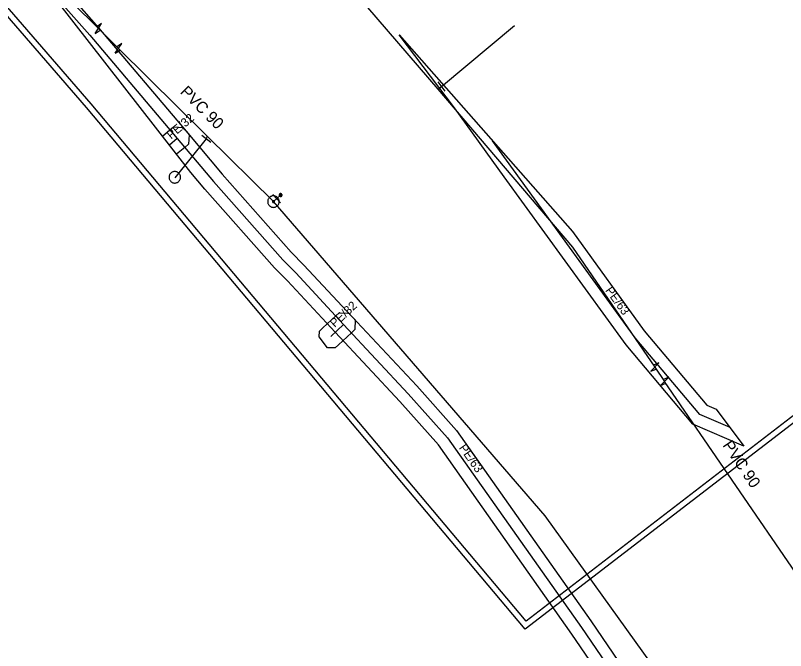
# Model space of a CAD drawing. Extents: x -743072 to -742584, y -978827 to -978325.
# Drawn here: x -742873.3 to -742806.2, y -978569.2 to -978513.9 of the extents above; entities that cross this region are included whole.
import ezdxf

# ---------------------------------------------------------------- set-up
doc = ezdxf.new("R2010")
doc.units = 0
for name, color, linetype in [('IS_CETIN_sdělovací kabel_nadz', 7, 'Continuous'), ('IS_GasNet_ochr pasmo', 7, 'Continuous'), ('IS_GasNet_plyn STL', 7, 'Continuous'), ('IS_Obec_kabel VO_nadz', 7, 'Continuous'), ('IS_popis_GasNet', 7, 'Continuous'), ('IS_popis_ScVK', 7, 'Continuous'), ('IS_ScVK_Kanal_dest', 7, 'Continuous'), ('IS_ScVK_Vodovod', 7, 'Continuous')]:
    doc.layers.add(name, color=color, linetype=linetype)

msp = doc.modelspace()

# ---------------------------------------------------------------- linework, layer by layer
at = {"layer": 'IS_CETIN_sdělovací kabel_nadz'}
msp.add_lwpolyline([(-742799.79, -978544.98), (-742828.86, -978567.32), (-742867.05, -978521.91), (-742897.64, -978486.54), (-742872.63, -978477.97), (-742862.09, -978471.14)], dxfattribs=at)
at = {"layer": 'IS_GasNet_ochr pasmo'}
for points in [[(-742816.226, -978580.321), (-742824.792, -978567.75), (-742836.414, -978551.283), (-742839.789, -978547.494), (-742845.41, -978541.465), (-742849.572, -978537.002), (-742850.702, -978535.852), (-742856.757, -978529.004), (-742857.983, -978527.554), (-742884.489, -978493.578)], [(-742875.214, -978504.506), (-742866.013, -978514.957), (-742858.394, -978523.968), (-742855.243, -978527.696), (-742849.238, -978534.488), (-742848.128, -978535.618), (-742843.948, -978540.101), (-742838.311, -978546.146), (-742834.846, -978550.037), (-742823.148, -978566.61), (-742814.434, -978579.399)]]:
    msp.add_lwpolyline(points, dxfattribs=at)
for points in [[(-742839.827, -978515.588), (-742824.755, -978532.708), (-742818.501, -978541.344), (-742813.057, -978547.815), (-742812.237, -978548.169), (-742809.823, -978551.387), (-742814.283, -978549.465), (-742820.079, -978542.576), (-742830.685, -978527.931), (-742835.034, -978521.925)], [(-742859.215, -978525.974), (-742860.447, -978524.395), (-742859.805, -978523.851), (-742859.489, -978523.583), (-742858.663, -978523.651), (-742858.395, -978523.967), (-742858.127, -978524.283), (-742858.195, -978525.109), (-742858.511, -978525.377)], [(-742846.072, -978542.821), (-742846.804, -978541.883), (-742846.787, -978541.381), (-742846.484, -978541.099), (-742845.361, -978540.052), (-742845.058, -978539.77), (-742844.23, -978539.798), (-742843.948, -978540.101), (-742843.666, -978540.404), (-742843.694, -978541.232), (-742843.997, -978541.514), (-742845.12, -978542.561), (-742845.423, -978542.843)]]:
    msp.add_lwpolyline(points, close=True, dxfattribs=at)
at = {"layer": 'IS_GasNet_plyn STL'}
for points in [[(-742871.432, -978510.314), (-742866.77, -978515.61), (-742859.158, -978524.614), (-742856, -978528.35), (-742849.97, -978535.17), (-742848.85, -978536.31), (-742844.679, -978540.783), (-742839.05, -978546.82), (-742835.63, -978550.66), (-742823.97, -978567.18), (-742815.33, -978579.86), (-742812.35, -978587.95), (-742808.39, -978596.31), (-742807.107, -978599.043), (-742807.09, -978599.08)], [(-742859.158, -978524.614), (-742859.831, -978525.185)], [(-742811.03, -978549.778), (-742813.67, -978548.64), (-742819.29, -978541.96), (-742829.875, -978527.344), (-742831.718, -978524.799)], [(-742844.679, -978540.783), (-742845.802, -978541.83)]]:
    msp.add_lwpolyline(points, dxfattribs=at)
at = {"layer": 'IS_Obec_kabel VO_nadz'}
msp.add_lwpolyline([(-742800.095, -978544.584), (-742828.785, -978566.632), (-742866.67, -978521.586), (-742896.777, -978486.773), (-742872.41, -978478.423), (-742861.818, -978471.56)], dxfattribs=at)
at = {"layer": 'IS_ScVK_Kanal_dest'}
for points in [[(-742836.467, -978520.3), (-742836.16, -978520.07)], [(-742856.548, -978524.401), (-742856.635, -978524.646)], [(-742850.787, -978530.098), (-742850.502, -978529.836)], [(-742850.502, -978529.836), (-742850.162, -978529.528)]]:
    msp.add_lwpolyline(points, dxfattribs=at)
at = {"layer": 'IS_ScVK_Vodovod'}
for points in [[(-742866.026, -978515.027), (-742875.324, -978505.832), (-742881.523, -978496.585), (-742891.202, -978483.542), (-742905.997, -978463.103), (-742924.708, -978451.984), (-742925.299, -978451.559), (-742925.477, -978451.431)], [(-742876.53, -978475.383), (-742870.143, -978481.198), (-742836.467, -978520.3), (-742824.743, -978534.055), (-742817.583, -978544.51)], [(-742866.307, -978515.451), (-742865.744, -978514.602)], [(-742865.744, -978514.602), (-742866.168, -978514.885)], [(-742866.307, -978515.451), (-742865.883, -978515.168)], [(-742866.026, -978515.027), (-742864.274, -978516.76)], [(-742836.16, -978520.07), (-742829.787, -978514.754)], [(-742864.555, -978517.184), (-742863.992, -978516.335)], [(-742863.992, -978516.335), (-742864.416, -978516.618)], [(-742864.555, -978517.184), (-742864.131, -978516.901)], [(-742850.787, -978530.098), (-742856.548, -978524.401), (-742864.274, -978516.76)], [(-742836.461, -978519.671), (-742835.859, -978520.469)], [(-742856.635, -978524.646), (-742859.372, -978528.015)], [(-742856.246, -978524.96), (-742857.022, -978524.33)], [(-742859.869, -978527.909), (-742859.874, -978527.96)], [(-742859.869, -978527.909), (-742859.874, -978527.96)], [(-742859.874, -978527.96), (-742859.872, -978528.013)], [(-742859.874, -978527.96), (-742859.872, -978528.013)], [(-742859.872, -978528.013), (-742859.868, -978528.065)], [(-742859.872, -978528.013), (-742859.868, -978528.065)], [(-742859.858, -978527.858), (-742859.869, -978527.909)], [(-742859.858, -978527.858), (-742859.869, -978527.909)], [(-742859.843, -978527.808), (-742859.858, -978527.858)], [(-742859.843, -978527.808), (-742859.858, -978527.858)], [(-742859.822, -978527.759), (-742859.843, -978527.808)], [(-742859.822, -978527.759), (-742859.843, -978527.808)], [(-742859.795, -978527.714), (-742859.822, -978527.759)], [(-742859.795, -978527.714), (-742859.822, -978527.759)], [(-742859.766, -978527.671), (-742859.795, -978527.714)], [(-742859.766, -978527.671), (-742859.795, -978527.714)], [(-742859.731, -978527.633), (-742859.766, -978527.671)], [(-742859.731, -978527.633), (-742859.766, -978527.671)], [(-742859.693, -978527.597), (-742859.731, -978527.633)], [(-742859.693, -978527.597), (-742859.731, -978527.633)], [(-742859.651, -978527.565), (-742859.693, -978527.597)], [(-742859.651, -978527.565), (-742859.693, -978527.597)], [(-742859.606, -978527.539), (-742859.651, -978527.565)], [(-742859.606, -978527.539), (-742859.651, -978527.565)], [(-742859.558, -978527.517), (-742859.606, -978527.539)], [(-742859.558, -978527.517), (-742859.606, -978527.539)], [(-742859.509, -978527.501), (-742859.558, -978527.517)], [(-742859.509, -978527.501), (-742859.558, -978527.517)], [(-742859.458, -978527.489), (-742859.509, -978527.501)], [(-742859.458, -978527.489), (-742859.509, -978527.501)], [(-742859.406, -978527.483), (-742859.458, -978527.489)], [(-742859.406, -978527.483), (-742859.458, -978527.489)], [(-742859.353, -978527.483), (-742859.406, -978527.483)], [(-742859.353, -978527.483), (-742859.406, -978527.483)], [(-742859.3, -978527.489), (-742859.353, -978527.483)], [(-742859.3, -978527.489), (-742859.353, -978527.483)], [(-742859.25, -978527.498), (-742859.3, -978527.489)], [(-742859.25, -978527.498), (-742859.3, -978527.489)], [(-742859.201, -978527.513), (-742859.25, -978527.498)], [(-742859.201, -978527.513), (-742859.25, -978527.498)], [(-742859.152, -978527.534), (-742859.201, -978527.513)], [(-742859.152, -978527.534), (-742859.201, -978527.513)], [(-742859.106, -978527.56), (-742859.152, -978527.534)], [(-742859.106, -978527.56), (-742859.152, -978527.534)], [(-742859.064, -978527.591), (-742859.106, -978527.56)], [(-742859.064, -978527.591), (-742859.106, -978527.56)], [(-742859.025, -978527.626), (-742859.064, -978527.591)], [(-742859.025, -978527.626), (-742859.064, -978527.591)], [(-742858.989, -978527.664), (-742859.025, -978527.626)], [(-742858.989, -978527.664), (-742859.025, -978527.626)], [(-742858.958, -978527.706), (-742858.989, -978527.664)], [(-742858.958, -978527.706), (-742858.989, -978527.664)], [(-742858.932, -978527.75), (-742858.958, -978527.706)], [(-742858.932, -978527.75), (-742858.958, -978527.706)], [(-742858.909, -978527.799), (-742858.932, -978527.75)], [(-742858.909, -978527.799), (-742858.932, -978527.75)], [(-742858.892, -978527.847), (-742858.909, -978527.799)], [(-742858.892, -978527.847), (-742858.909, -978527.799)], [(-742858.882, -978527.898), (-742858.892, -978527.847)], [(-742858.882, -978527.898), (-742858.892, -978527.847)], [(-742858.89, -978528.108), (-742858.879, -978528.056)], [(-742858.89, -978528.108), (-742858.879, -978528.056)], [(-742858.876, -978527.951), (-742858.882, -978527.898)], [(-742858.876, -978527.951), (-742858.882, -978527.898)], [(-742858.879, -978528.056), (-742858.875, -978528.003)], [(-742858.879, -978528.056), (-742858.875, -978528.003)], [(-742858.875, -978528.003), (-742858.876, -978527.951)], [(-742858.875, -978528.003), (-742858.876, -978527.951)], [(-742859.868, -978528.065), (-742859.856, -978528.115)], [(-742859.868, -978528.065), (-742859.856, -978528.115)], [(-742859.856, -978528.115), (-742859.84, -978528.166)], [(-742859.856, -978528.115), (-742859.84, -978528.166)], [(-742859.84, -978528.166), (-742859.818, -978528.214)], [(-742859.84, -978528.166), (-742859.818, -978528.214)], [(-742859.818, -978528.214), (-742859.791, -978528.259)], [(-742859.818, -978528.214), (-742859.791, -978528.259)], [(-742859.791, -978528.259), (-742859.759, -978528.3)], [(-742859.791, -978528.259), (-742859.759, -978528.3)], [(-742859.759, -978528.3), (-742859.724, -978528.339)], [(-742859.759, -978528.3), (-742859.724, -978528.339)], [(-742859.724, -978528.339), (-742859.686, -978528.374)], [(-742859.724, -978528.339), (-742859.686, -978528.374)], [(-742859.686, -978528.374), (-742859.643, -978528.405)], [(-742859.686, -978528.374), (-742859.643, -978528.405)], [(-742859.643, -978528.405), (-742859.597, -978528.431)], [(-742859.643, -978528.405), (-742859.597, -978528.431)], [(-742859.597, -978528.431), (-742859.549, -978528.45)], [(-742859.597, -978528.431), (-742859.549, -978528.45)], [(-742859.549, -978528.45), (-742859.499, -978528.466)], [(-742859.549, -978528.45), (-742859.499, -978528.466)], [(-742859.499, -978528.466), (-742859.448, -978528.476)], [(-742859.499, -978528.466), (-742859.448, -978528.476)], [(-742859.448, -978528.476), (-742859.395, -978528.481)], [(-742859.448, -978528.476), (-742859.395, -978528.481)], [(-742859.395, -978528.481), (-742859.344, -978528.48)], [(-742859.395, -978528.481), (-742859.344, -978528.48)], [(-742859.344, -978528.48), (-742859.292, -978528.474)], [(-742859.344, -978528.48), (-742859.292, -978528.474)], [(-742859.292, -978528.474), (-742859.241, -978528.463)], [(-742859.292, -978528.474), (-742859.241, -978528.463)], [(-742859.241, -978528.463), (-742859.191, -978528.447)], [(-742859.241, -978528.463), (-742859.191, -978528.447)], [(-742859.191, -978528.447), (-742859.143, -978528.426)], [(-742859.191, -978528.447), (-742859.143, -978528.426)], [(-742859.143, -978528.426), (-742859.098, -978528.398)], [(-742859.143, -978528.426), (-742859.098, -978528.398)], [(-742859.098, -978528.398), (-742859.056, -978528.368)], [(-742859.098, -978528.398), (-742859.056, -978528.368)], [(-742859.056, -978528.368), (-742859.018, -978528.332)], [(-742859.056, -978528.368), (-742859.018, -978528.332)], [(-742859.018, -978528.332), (-742858.983, -978528.294)], [(-742859.018, -978528.332), (-742858.983, -978528.294)], [(-742858.983, -978528.294), (-742858.952, -978528.249)], [(-742858.983, -978528.294), (-742858.952, -978528.249)], [(-742858.952, -978528.249), (-742858.927, -978528.206)], [(-742858.952, -978528.249), (-742858.927, -978528.206)], [(-742858.927, -978528.206), (-742858.906, -978528.156)], [(-742858.927, -978528.206), (-742858.906, -978528.156)], [(-742858.906, -978528.156), (-742858.89, -978528.108)], [(-742858.906, -978528.156), (-742858.89, -978528.108)], [(-742850.287, -978530.098), (-742850.29, -978530.046), (-742850.298, -978529.994), (-742850.312, -978529.944), (-742850.33, -978529.895), (-742850.354, -978529.848), (-742850.383, -978529.804), (-742850.416, -978529.764), (-742850.453, -978529.727), (-742850.493, -978529.694), (-742850.537, -978529.665), (-742850.584, -978529.641), (-742850.633, -978529.623), (-742850.683, -978529.609), (-742850.735, -978529.601), (-742850.787, -978529.598), (-742850.839, -978529.601), (-742850.891, -978529.609), (-742850.942, -978529.623), (-742850.99, -978529.641), (-742851.037, -978529.665), (-742851.081, -978529.694), (-742851.122, -978529.727), (-742851.159, -978529.764), (-742851.192, -978529.804), (-742851.22, -978529.848), (-742851.244, -978529.895), (-742851.263, -978529.944), (-742851.276, -978529.994), (-742851.284, -978530.046), (-742851.287, -978530.098), (-742851.284, -978530.15), (-742851.276, -978530.202), (-742851.263, -978530.253), (-742851.244, -978530.301), (-742851.22, -978530.348), (-742851.192, -978530.392), (-742851.159, -978530.433), (-742851.122, -978530.47), (-742851.081, -978530.503), (-742851.037, -978530.531), (-742850.99, -978530.555), (-742850.942, -978530.574), (-742850.891, -978530.587), (-742850.839, -978530.595), (-742850.787, -978530.598), (-742850.735, -978530.595), (-742850.683, -978530.587), (-742850.633, -978530.574), (-742850.584, -978530.555), (-742850.537, -978530.531), (-742850.493, -978530.503), (-742850.453, -978530.47), (-742850.416, -978530.433), (-742850.383, -978530.392), (-742850.354, -978530.348), (-742850.33, -978530.301), (-742850.312, -978530.253), (-742850.298, -978530.202), (-742850.29, -978530.15), (-742850.287, -978530.098)], [(-742850.705, -978530.098), (-742850.705, -978530.089), (-742850.707, -978530.081), (-742850.709, -978530.073), (-742850.712, -978530.065), (-742850.716, -978530.057), (-742850.721, -978530.05), (-742850.726, -978530.043), (-742850.732, -978530.037), (-742850.739, -978530.032), (-742850.746, -978530.027), (-742850.754, -978530.023), (-742850.762, -978530.02), (-742850.77, -978530.018), (-742850.778, -978530.016), (-742850.787, -978530.016), (-742850.796, -978530.016), (-742850.804, -978530.018), (-742850.812, -978530.02), (-742850.82, -978530.023), (-742850.828, -978530.027), (-742850.835, -978530.032), (-742850.842, -978530.037), (-742850.848, -978530.043), (-742850.854, -978530.05), (-742850.858, -978530.057), (-742850.862, -978530.065), (-742850.865, -978530.073), (-742850.867, -978530.081), (-742850.869, -978530.089), (-742850.869, -978530.098), (-742850.869, -978530.107), (-742850.867, -978530.115), (-742850.865, -978530.123), (-742850.862, -978530.131), (-742850.858, -978530.139), (-742850.854, -978530.146), (-742850.848, -978530.153), (-742850.842, -978530.159), (-742850.835, -978530.165), (-742850.828, -978530.169), (-742850.82, -978530.173), (-742850.812, -978530.176), (-742850.804, -978530.178), (-742850.796, -978530.18), (-742850.787, -978530.18), (-742850.778, -978530.18), (-742850.77, -978530.178), (-742850.762, -978530.176), (-742850.754, -978530.173), (-742850.746, -978530.169), (-742850.739, -978530.165), (-742850.732, -978530.159), (-742850.726, -978530.153), (-742850.721, -978530.146), (-742850.716, -978530.139), (-742850.712, -978530.131), (-742850.709, -978530.123), (-742850.707, -978530.115), (-742850.705, -978530.107), (-742850.705, -978530.098)], [(-742850.84, -978529.467), (-742850.164, -978530.205)], [(-742850.288, -978529.528), (-742850.288, -978529.541), (-742850.286, -978529.554), (-742850.283, -978529.567), (-742850.278, -978529.579), (-742850.272, -978529.591), (-742850.265, -978529.602), (-742850.257, -978529.612), (-742850.247, -978529.622), (-742850.237, -978529.63), (-742850.226, -978529.637), (-742850.214, -978529.643), (-742850.202, -978529.648), (-742850.189, -978529.651), (-742850.176, -978529.653), (-742850.163, -978529.655), (-742850.15, -978529.654), (-742850.137, -978529.652), (-742850.124, -978529.649), (-742850.112, -978529.644), (-742850.1, -978529.638), (-742850.089, -978529.631), (-742850.079, -978529.623), (-742850.069, -978529.613), (-742850.061, -978529.603), (-742850.054, -978529.592), (-742850.048, -978529.58), (-742850.043, -978529.568), (-742850.04, -978529.555), (-742850.038, -978529.542), (-742850.036, -978529.529), (-742850.037, -978529.516), (-742850.039, -978529.503), (-742850.042, -978529.49), (-742850.047, -978529.478), (-742850.053, -978529.466), (-742850.06, -978529.455), (-742850.068, -978529.445), (-742850.078, -978529.435), (-742850.088, -978529.427), (-742850.099, -978529.42), (-742850.111, -978529.414), (-742850.123, -978529.409), (-742850.136, -978529.406), (-742850.149, -978529.404), (-742850.162, -978529.403), (-742850.175, -978529.403), (-742850.188, -978529.405), (-742850.201, -978529.408), (-742850.213, -978529.413), (-742850.225, -978529.419), (-742850.236, -978529.426), (-742850.246, -978529.434), (-742850.256, -978529.444), (-742850.264, -978529.454), (-742850.271, -978529.465), (-742850.277, -978529.477), (-742850.282, -978529.489), (-742850.285, -978529.502), (-742850.287, -978529.515), (-742850.288, -978529.528)], [(-742850.268, -978529.528), (-742850.269, -978529.539), (-742850.267, -978529.55), (-742850.264, -978529.561), (-742850.26, -978529.571), (-742850.255, -978529.581), (-742850.249, -978529.59), (-742850.242, -978529.599), (-742850.234, -978529.607), (-742850.225, -978529.614), (-742850.216, -978529.62), (-742850.206, -978529.625), (-742850.196, -978529.629), (-742850.185, -978529.632), (-742850.174, -978529.635), (-742850.163, -978529.635), (-742850.152, -978529.635), (-742850.141, -978529.633), (-742850.13, -978529.63), (-742850.12, -978529.626), (-742850.11, -978529.621), (-742850.101, -978529.615), (-742850.092, -978529.608), (-742850.084, -978529.6), (-742850.077, -978529.591), (-742850.071, -978529.582), (-742850.066, -978529.572), (-742850.062, -978529.562), (-742850.059, -978529.551), (-742850.057, -978529.54), (-742850.056, -978529.529), (-742850.056, -978529.518), (-742850.058, -978529.507), (-742850.061, -978529.496), (-742850.065, -978529.486), (-742850.07, -978529.476), (-742850.076, -978529.467), (-742850.083, -978529.458), (-742850.091, -978529.45), (-742850.1, -978529.443), (-742850.109, -978529.437), (-742850.119, -978529.432), (-742850.129, -978529.428), (-742850.14, -978529.425), (-742850.151, -978529.423), (-742850.162, -978529.423), (-742850.173, -978529.422), (-742850.184, -978529.424), (-742850.195, -978529.427), (-742850.205, -978529.431), (-742850.215, -978529.436), (-742850.224, -978529.442), (-742850.233, -978529.449), (-742850.241, -978529.457), (-742850.248, -978529.466), (-742850.254, -978529.475), (-742850.259, -978529.485), (-742850.263, -978529.495), (-742850.266, -978529.506), (-742850.268, -978529.517), (-742850.268, -978529.528)], [(-742850.249, -978529.528), (-742850.249, -978529.537), (-742850.248, -978529.546), (-742850.245, -978529.555), (-742850.242, -978529.563), (-742850.238, -978529.571), (-742850.233, -978529.579), (-742850.227, -978529.586), (-742850.221, -978529.592), (-742850.214, -978529.598), (-742850.206, -978529.603), (-742850.198, -978529.607), (-742850.19, -978529.61), (-742850.181, -978529.613), (-742850.172, -978529.614), (-742850.163, -978529.616), (-742850.154, -978529.615), (-742850.145, -978529.614), (-742850.136, -978529.611), (-742850.128, -978529.608), (-742850.12, -978529.604), (-742850.112, -978529.599), (-742850.105, -978529.593), (-742850.099, -978529.587), (-742850.093, -978529.58), (-742850.088, -978529.572), (-742850.084, -978529.564), (-742850.081, -978529.556), (-742850.078, -978529.547), (-742850.077, -978529.538), (-742850.075, -978529.529), (-742850.076, -978529.52), (-742850.077, -978529.511), (-742850.08, -978529.502), (-742850.083, -978529.494), (-742850.087, -978529.486), (-742850.092, -978529.478), (-742850.098, -978529.471), (-742850.104, -978529.465), (-742850.111, -978529.459), (-742850.119, -978529.454), (-742850.127, -978529.45), (-742850.135, -978529.447), (-742850.144, -978529.444), (-742850.153, -978529.443), (-742850.162, -978529.442), (-742850.171, -978529.442), (-742850.18, -978529.443), (-742850.189, -978529.446), (-742850.197, -978529.449), (-742850.205, -978529.453), (-742850.213, -978529.458), (-742850.22, -978529.464), (-742850.226, -978529.47), (-742850.232, -978529.477), (-742850.237, -978529.485), (-742850.241, -978529.493), (-742850.244, -978529.501), (-742850.247, -978529.51), (-742850.248, -978529.519), (-742850.249, -978529.528)], [(-742850.229, -978529.528), (-742850.229, -978529.535), (-742850.228, -978529.542), (-742850.227, -978529.549), (-742850.224, -978529.555), (-742850.221, -978529.561), (-742850.217, -978529.567), (-742850.213, -978529.573), (-742850.208, -978529.578), (-742850.202, -978529.582), (-742850.196, -978529.586), (-742850.19, -978529.589), (-742850.184, -978529.592), (-742850.177, -978529.593), (-742850.17, -978529.596), (-742850.163, -978529.596), (-742850.156, -978529.596), (-742850.149, -978529.594), (-742850.142, -978529.593), (-742850.136, -978529.59), (-742850.129, -978529.587), (-742850.124, -978529.583), (-742850.118, -978529.579), (-742850.113, -978529.574), (-742850.109, -978529.568), (-742850.105, -978529.562), (-742850.102, -978529.556), (-742850.099, -978529.55), (-742850.097, -978529.543), (-742850.096, -978529.536), (-742850.095, -978529.529), (-742850.095, -978529.522), (-742850.096, -978529.515), (-742850.098, -978529.508), (-742850.101, -978529.502), (-742850.104, -978529.495), (-742850.108, -978529.49), (-742850.112, -978529.484), (-742850.117, -978529.479), (-742850.123, -978529.475), (-742850.128, -978529.471), (-742850.135, -978529.468), (-742850.141, -978529.465), (-742850.148, -978529.463), (-742850.155, -978529.462), (-742850.162, -978529.462), (-742850.169, -978529.462), (-742850.176, -978529.462), (-742850.183, -978529.464), (-742850.189, -978529.467), (-742850.195, -978529.47), (-742850.201, -978529.474), (-742850.207, -978529.478), (-742850.212, -978529.483), (-742850.216, -978529.489), (-742850.22, -978529.494), (-742850.223, -978529.501), (-742850.226, -978529.507), (-742850.227, -978529.514), (-742850.229, -978529.521), (-742850.229, -978529.528)], [(-742850.209, -978529.528), (-742850.209, -978529.533), (-742850.209, -978529.538), (-742850.208, -978529.543), (-742850.206, -978529.547), (-742850.204, -978529.552), (-742850.201, -978529.556), (-742850.198, -978529.559), (-742850.194, -978529.563), (-742850.191, -978529.566), (-742850.187, -978529.569), (-742850.182, -978529.571), (-742850.178, -978529.573), (-742850.173, -978529.574), (-742850.168, -978529.576), (-742850.163, -978529.576), (-742850.158, -978529.576), (-742850.153, -978529.575), (-742850.148, -978529.574), (-742850.144, -978529.572), (-742850.139, -978529.57), (-742850.135, -978529.567), (-742850.131, -978529.564), (-742850.128, -978529.56), (-742850.125, -978529.557), (-742850.122, -978529.553), (-742850.12, -978529.548), (-742850.118, -978529.544), (-742850.117, -978529.539), (-742850.116, -978529.534), (-742850.115, -978529.529), (-742850.115, -978529.524), (-742850.116, -978529.519), (-742850.117, -978529.514), (-742850.119, -978529.51), (-742850.121, -978529.505), (-742850.124, -978529.501), (-742850.127, -978529.497), (-742850.13, -978529.494), (-742850.134, -978529.491), (-742850.138, -978529.488), (-742850.143, -978529.486), (-742850.147, -978529.484), (-742850.152, -978529.483), (-742850.157, -978529.482), (-742850.162, -978529.482), (-742850.167, -978529.482), (-742850.172, -978529.483), (-742850.177, -978529.483), (-742850.181, -978529.485), (-742850.186, -978529.487), (-742850.19, -978529.49), (-742850.193, -978529.493), (-742850.197, -978529.496), (-742850.2, -978529.5), (-742850.203, -978529.504), (-742850.205, -978529.509), (-742850.207, -978529.513), (-742850.208, -978529.518), (-742850.209, -978529.523), (-742850.209, -978529.528)], [(-742850.189, -978529.528), (-742850.189, -978529.531), (-742850.19, -978529.534), (-742850.189, -978529.536), (-742850.188, -978529.539), (-742850.187, -978529.542), (-742850.185, -978529.544), (-742850.183, -978529.546), (-742850.181, -978529.548), (-742850.179, -978529.55), (-742850.177, -978529.552), (-742850.174, -978529.554), (-742850.171, -978529.555), (-742850.169, -978529.555), (-742850.166, -978529.556), (-742850.163, -978529.556), (-742850.16, -978529.556), (-742850.157, -978529.556), (-742850.154, -978529.555), (-742850.152, -978529.554), (-742850.149, -978529.553), (-742850.147, -978529.551), (-742850.144, -978529.549), (-742850.142, -978529.547), (-742850.141, -978529.545), (-742850.139, -978529.543), (-742850.138, -978529.54), (-742850.136, -978529.537), (-742850.136, -978529.535), (-742850.135, -978529.532), (-742850.134, -978529.529), (-742850.135, -978529.526), (-742850.135, -978529.523), (-742850.136, -978529.52), (-742850.137, -978529.518), (-742850.138, -978529.515), (-742850.14, -978529.513), (-742850.141, -978529.51), (-742850.143, -978529.508), (-742850.146, -978529.507), (-742850.148, -978529.505), (-742850.151, -978529.504), (-742850.153, -978529.503), (-742850.156, -978529.502), (-742850.159, -978529.502), (-742850.162, -978529.501), (-742850.165, -978529.502), (-742850.168, -978529.501), (-742850.17, -978529.503), (-742850.173, -978529.503), (-742850.176, -978529.504), (-742850.178, -978529.506), (-742850.18, -978529.507), (-742850.182, -978529.509), (-742850.184, -978529.512), (-742850.186, -978529.514), (-742850.187, -978529.517), (-742850.188, -978529.519), (-742850.189, -978529.522), (-742850.189, -978529.525), (-742850.189, -978529.528)], [(-742850.17, -978529.528), (-742850.17, -978529.53), (-742850.17, -978529.53), (-742850.169, -978529.53), (-742850.169, -978529.532), (-742850.17, -978529.533), (-742850.168, -978529.533), (-742850.168, -978529.533), (-742850.168, -978529.535), (-742850.168, -978529.535), (-742850.167, -978529.536), (-742850.165, -978529.536), (-742850.165, -978529.536), (-742850.165, -978529.537), (-742850.163, -978529.537), (-742850.163, -978529.537), (-742850.162, -978529.537), (-742850.161, -978529.537), (-742850.161, -978529.536), (-742850.16, -978529.536), (-742850.158, -978529.536), (-742850.158, -978529.535), (-742850.158, -978529.535), (-742850.157, -978529.534), (-742850.157, -978529.534), (-742850.155, -978529.533), (-742850.155, -978529.532), (-742850.154, -978529.531), (-742850.154, -978529.531), (-742850.154, -978529.53), (-742850.154, -978529.529), (-742850.154, -978529.528), (-742850.154, -978529.527), (-742850.154, -978529.527), (-742850.155, -978529.526), (-742850.155, -978529.525), (-742850.156, -978529.524), (-742850.156, -978529.524), (-742850.157, -978529.523), (-742850.157, -978529.523), (-742850.158, -978529.522), (-742850.159, -978529.522), (-742850.16, -978529.521), (-742850.16, -978529.521), (-742850.161, -978529.521), (-742850.162, -978529.521), (-742850.163, -978529.521), (-742850.164, -978529.521), (-742850.164, -978529.521), (-742850.165, -978529.522), (-742850.166, -978529.521), (-742850.167, -978529.523), (-742850.167, -978529.523), (-742850.168, -978529.523), (-742850.168, -978529.523), (-742850.169, -978529.525), (-742850.169, -978529.526), (-742850.169, -978529.527), (-742850.17, -978529.527), (-742850.17, -978529.528), (-742850.17, -978529.528)], [(-742799.35, -978596.101), (-742827.12, -978557.465), (-742850.787, -978530.098)], [(-742817.225, -978544.146), (-742817.94, -978544.873)], [(-742817.225, -978544.146), (-742817.696, -978544.344)], [(-742817.94, -978544.873), (-742817.469, -978544.675)], [(-742817.583, -978544.51), (-742816.724, -978545.748)], [(-742817.08, -978546.111), (-742816.367, -978545.384)], [(-742816.367, -978545.384), (-742816.837, -978545.582)], [(-742817.08, -978546.111), (-742816.61, -978545.913)], [(-742804.943, -978562.941), (-742816.729, -978545.749)]]:
    msp.add_lwpolyline(points, dxfattribs=at)

# ---------------------------------------------------------------- texts
at = {"layer": 'IS_popis_GasNet'}
for s, rotation, p in [('PE/32', 40.29304, (-742859.695, -978524.699)), ('PE/63', 305.91229, (-742821.93, -978537.838)), ('PE/32', 42.99415, (-742845.441, -978541.107)), ('PE/63', 305.21487, (-742834.668, -978551.54))]:
    msp.add_text(s, height=0.75, rotation=rotation, dxfattribs=at).set_placement(p)
at = {"layer": 'IS_popis_ScVK'}
for rotation, p in [(315, (-742858.971, -978520.619)), (304, (-742811.719, -978551.313))]:
    msp.add_text('PVC 90', height=1, rotation=rotation, dxfattribs=at).set_placement(p)

doc.saveas('drawing.dxf')
